// Mitsubishi GX Works2 project: 3U   485-1口 MODBUS RTU 从站   PLC: FX3U/FX3UC

PROGRAM MAIN
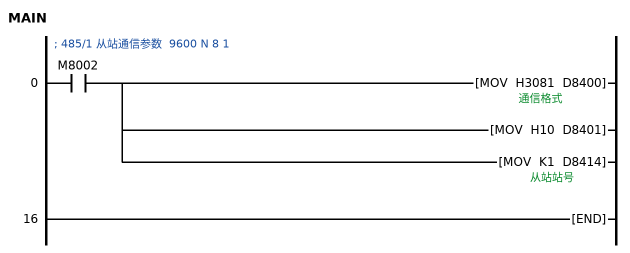
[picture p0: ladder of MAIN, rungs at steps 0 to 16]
; 485/1 从站通信参数  9600 N 8 1
0     LD      M8002
      MOV     H3081 D8400  ; 通信格式
      MOV     H10 D8401
      MOV     K1 D8414  ; 从站站号
16    END
END_PROGRAM
